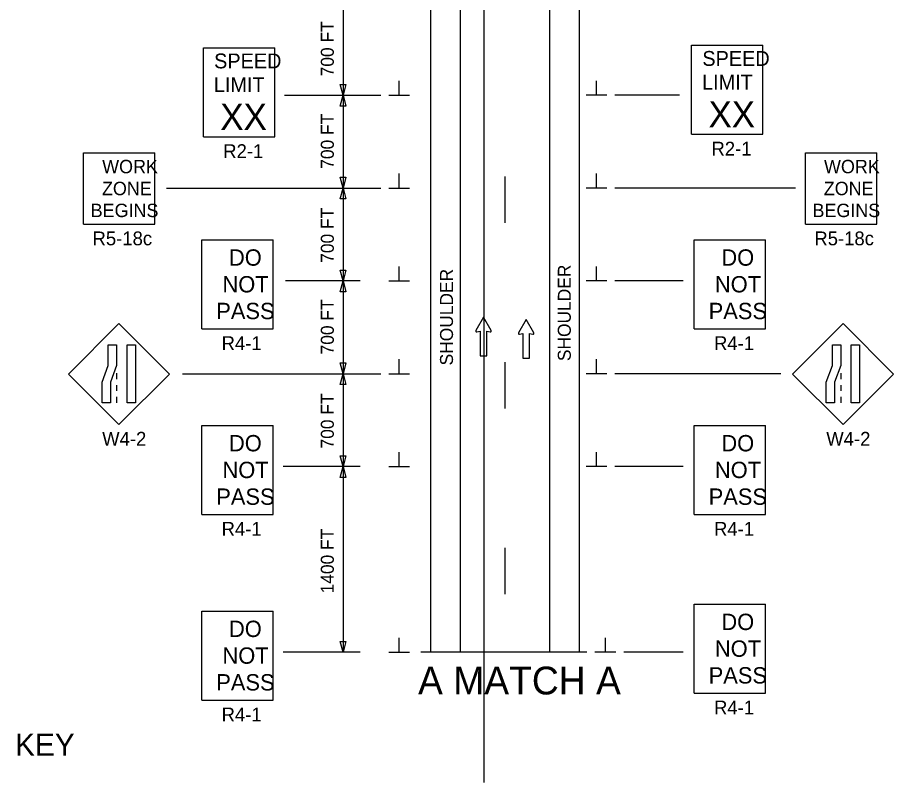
# Model space of a CAD drawing. Extents: x 15273 to 18137, y 1908 to 6555.
# Drawn here: x 15330.6 to 15802.3, y 2408.6 to 2820.6 of the extents above; entities that cross this region are included whole.
import ezdxf

# ---------------------------------------------------------------- set-up
doc = ezdxf.new("R2010")
doc.units = 0
for name, color, linetype in [('ALI_LEGAL_EX', 7, 'Continuous'), ('MT_SCRATCH_LEVEL_E', 7, 'Continuous'), ('PAVT_EDGE_EX', 7, 'Continuous'), ('TRAFFIC_SIGNS_PR', 7, 'Continuous'), ('TYPICAL_TEXT_DIMEN_EX', 7, 'Continuous'), ('TYPICAL_TEXT_DIMEN_PR', 7, 'Continuous')]:
    doc.layers.add(name, color=color, linetype=linetype)

msp = doc.modelspace()

# ---------------------------------------------------------------- linework, layer by layer
at = {"layer": 'ALI_LEGAL_EX'}
msp.add_line((15581.68, 3237.79), (15581.68, 2408.6), dxfattribs=at)
for points in [[(15593, 2735), (15593, 2710)], [(15593, 2635), (15593, 2610)], [(15593, 2535), (15593, 2510)]]:
    msp.add_lwpolyline(points, dxfattribs=at)
at = {"layer": 'MT_SCRATCH_LEVEL_E'}
for p, q in [((15581.51, 2659.29), (15577.39, 2652.05)), ((15585.65, 2652.05), (15581.51, 2659.29)), ((15604.48, 2658.02), (15600.37, 2650.78)), ((15608.63, 2650.78), (15604.48, 2658.02)), ((15577.88, 2651.37), (15579.65, 2651.68)), ((15579.65, 2651.68), (15579.65, 2638.43)), ((15583.4, 2638.43), (15583.4, 2651.68)), ((15583.4, 2651.68), (15585.17, 2651.37)), ((15600.85, 2650.1), (15602.63, 2650.41)), ((15602.63, 2650.41), (15602.63, 2637.16)), ((15606.37, 2637.16), (15606.37, 2650.41)), ((15606.37, 2650.41), (15608.15, 2650.1)), ((15579.65, 2638.43), (15583.4, 2638.43)), ((15602.63, 2637.16), (15606.37, 2637.16))]:
    msp.add_line(p, q, dxfattribs=at)
for centre, start, end in [((15577.8, 2651.83), 150.4248, 279.9638), ((15585.24, 2651.83), 260.0362, 29.7731), ((15600.78, 2650.56), 150.4248, 279.9638), ((15608.22, 2650.56), 260.0362, 29.7731)]:
    msp.add_arc(centre, 0.463, start, end, dxfattribs=at)
at = {"layer": 'PAVT_EDGE_EX'}
for p, q in [((15553, 3162.29), (15553, 2478.74)), ((15569, 3162.29), (15569, 2478.74)), ((15617, 3162.29), (15617, 2478.74)), ((15633, 3163.21), (15633, 2478.74))]:
    msp.add_line(p, q, dxfattribs=at)
at = {"layer": 'TRAFFIC_SIGNS_PR'}
for p, q in [((15430.69, 2804.37), (15469.09, 2804.37)), ((15430.69, 2756.37), (15430.69, 2804.37)), ((15469.09, 2756.37), (15469.09, 2804.37)), ((15693.59, 2805.71), (15731.99, 2805.71)), ((15693.59, 2757.71), (15693.59, 2805.71)), ((15731.99, 2757.71), (15731.99, 2805.71)), ((15430.69, 2756.37), (15469.09, 2756.37)), ((15693.59, 2757.71), (15731.99, 2757.71)), ((15366.19, 2709.37), (15366.19, 2747.77)), ((15366.19, 2747.77), (15404.59, 2747.77)), ((15404.59, 2709.37), (15404.59, 2747.77)), ((15754.87, 2709.37), (15754.87, 2747.77)), ((15754.87, 2747.77), (15793.27, 2747.77)), ((15793.27, 2709.37), (15793.27, 2747.77)), ((15366.19, 2709.37), (15404.59, 2709.37)), ((15754.87, 2709.37), (15793.27, 2709.37)), ((15429.84, 2652.95), (15429.84, 2700.95)), ((15429.84, 2700.95), (15468.24, 2700.95)), ((15468.24, 2652.95), (15468.24, 2700.95)), ((15694.98, 2652.95), (15694.98, 2700.95)), ((15694.98, 2700.95), (15733.38, 2700.95)), ((15733.38, 2652.95), (15733.38, 2700.95)), ((15385.23, 2655.75), (15358.07, 2628.6)), ((15412.38, 2628.6), (15385.23, 2655.75)), ((15775.13, 2655.75), (15747.98, 2628.6)), ((15802.28, 2628.6), (15775.13, 2655.75)), ((15429.84, 2652.95), (15468.24, 2652.95)), ((15694.98, 2652.95), (15733.38, 2652.95)), ((15358.07, 2628.6), (15385.23, 2601.45)), ((15383.98, 2629.09), (15383.98, 2625.89)), ((15385.23, 2601.45), (15412.38, 2628.6)), ((15747.98, 2628.6), (15775.13, 2601.45)), ((15773.88, 2629.09), (15773.88, 2625.89)), ((15775.13, 2601.45), (15802.28, 2628.6)), ((15383.98, 2622.69), (15383.98, 2619.49)), ((15773.88, 2622.69), (15773.88, 2619.49)), ((15383.98, 2616.29), (15383.98, 2613.09)), ((15773.88, 2616.29), (15773.88, 2613.09)), ((15429.84, 2552.95), (15429.84, 2600.95)), ((15429.84, 2600.95), (15468.24, 2600.95)), ((15468.24, 2552.95), (15468.24, 2600.95)), ((15694.98, 2552.95), (15694.98, 2600.95)), ((15694.98, 2600.95), (15733.38, 2600.95)), ((15733.38, 2552.95), (15733.38, 2600.95)), ((15429.84, 2552.95), (15468.24, 2552.95)), ((15694.98, 2552.95), (15733.38, 2552.95)), ((15694.98, 2456.71), (15694.98, 2504.71)), ((15694.98, 2504.71), (15733.38, 2504.71)), ((15733.38, 2456.71), (15733.38, 2504.71)), ((15429.84, 2452.95), (15429.84, 2500.95)), ((15429.84, 2500.95), (15468.24, 2500.95)), ((15468.24, 2452.95), (15468.24, 2500.95)), ((15429.84, 2452.95), (15468.24, 2452.95)), ((15694.98, 2456.71), (15733.38, 2456.71))]:
    msp.add_line(p, q, dxfattribs=at)
for points in [[(15383.98, 2644.34), (15383.98, 2633.15), (15380.63, 2624.27), (15380.63, 2613.09), (15376.14, 2613.09), (15376.14, 2624.27), (15379.49, 2633.15), (15379.49, 2644.34)], [(15394.11, 2644.34), (15394.11, 2613.09), (15389.62, 2613.09), (15389.62, 2644.34)], [(15773.88, 2644.34), (15773.88, 2633.15), (15770.54, 2624.27), (15770.54, 2613.09), (15766.04, 2613.09), (15766.04, 2624.27), (15769.39, 2633.15), (15769.39, 2644.34)], [(15784.02, 2644.34), (15784.02, 2613.09), (15779.52, 2613.09), (15779.52, 2644.34)]]:
    msp.add_lwpolyline(points, close=True, dxfattribs=at)
at = {"layer": 'TYPICAL_TEXT_DIMEN_PR'}
for p, q in [((15505.88, 2828.74), (15505.88, 2778.74)), ((15505.88, 2778.74), (15504.31, 2784.61)), ((15504.31, 2784.61), (15505.88, 2784.61)), ((15505.88, 2784.61), (15507.45, 2784.61)), ((15507.45, 2784.61), (15505.88, 2778.74)), ((15536.12, 2778.74), (15536.12, 2786.53)), ((15642.37, 2778.74), (15642.37, 2786.53)), ((15474.36, 2778.74), (15526.25, 2778.74)), ((15504.31, 2772.88), (15505.88, 2778.74)), ((15504.31, 2772.88), (15505.88, 2778.74)), ((15505.88, 2778.74), (15505.88, 2728.74)), ((15505.88, 2778.74), (15507.45, 2772.88)), ((15505.88, 2778.74), (15507.45, 2772.88)), ((15530.5, 2778.74), (15541.75, 2778.74)), ((15648, 2778.74), (15636.75, 2778.74)), ((15687.08, 2778.74), (15652.25, 2778.74)), ((15505.88, 2772.88), (15504.31, 2772.88)), ((15505.88, 2772.88), (15504.31, 2772.88)), ((15507.45, 2772.88), (15505.88, 2772.88)), ((15507.45, 2772.88), (15505.88, 2772.88)), ((15536.12, 2728.74), (15536.12, 2736.53)), ((15642.37, 2728.74), (15642.37, 2736.53)), ((15505.88, 2728.74), (15504.31, 2734.61)), ((15504.31, 2734.61), (15505.88, 2734.61)), ((15505.88, 2728.74), (15504.31, 2734.61)), ((15504.31, 2734.61), (15505.88, 2734.61)), ((15505.88, 2734.61), (15507.45, 2734.61)), ((15507.45, 2734.61), (15505.88, 2728.74)), ((15505.88, 2734.61), (15507.45, 2734.61)), ((15507.45, 2734.61), (15505.88, 2728.74)), ((15410.88, 2728.74), (15526.25, 2728.74)), ((15504.31, 2722.88), (15505.88, 2728.74)), ((15505.88, 2728.74), (15505.88, 2678.74)), ((15505.88, 2728.74), (15507.45, 2722.88)), ((15530.5, 2728.74), (15541.75, 2728.74)), ((15648, 2728.74), (15636.75, 2728.74)), ((15749.59, 2728.74), (15652.25, 2728.74)), ((15505.88, 2722.88), (15504.31, 2722.88)), ((15507.45, 2722.88), (15505.88, 2722.88)), ((15505.88, 2678.74), (15504.31, 2684.61)), ((15504.31, 2684.61), (15505.88, 2684.61)), ((15505.88, 2684.61), (15507.45, 2684.61)), ((15507.45, 2684.61), (15505.88, 2678.74)), ((15536.12, 2678.74), (15536.12, 2686.53)), ((15642.37, 2678.74), (15642.37, 2686.53)), ((15515.11, 2678.74), (15474.99, 2678.74)), ((15504.31, 2672.88), (15505.88, 2678.74)), ((15505.88, 2678.74), (15505.88, 2628.74)), ((15505.88, 2678.74), (15507.45, 2672.88)), ((15530.5, 2678.74), (15541.75, 2678.74)), ((15648, 2678.74), (15636.75, 2678.74)), ((15688.96, 2678.74), (15652.25, 2678.74)), ((15505.88, 2672.88), (15504.31, 2672.88)), ((15507.45, 2672.88), (15505.88, 2672.88)), ((15505.88, 2628.74), (15504.31, 2634.61)), ((15504.31, 2634.61), (15505.88, 2634.61)), ((15505.88, 2628.74), (15504.31, 2634.61)), ((15504.31, 2634.61), (15505.88, 2634.61)), ((15505.88, 2634.61), (15507.45, 2634.61)), ((15507.45, 2634.61), (15505.88, 2628.74)), ((15505.88, 2634.61), (15507.45, 2634.61)), ((15507.45, 2634.61), (15505.88, 2628.74)), ((15536.12, 2628.74), (15536.12, 2636.53)), ((15642.37, 2628.74), (15642.37, 2636.53)), ((15419.37, 2628.74), (15526.25, 2628.74)), ((15504.31, 2622.88), (15505.88, 2628.74)), ((15505.88, 2628.74), (15505.88, 2578.74)), ((15505.88, 2628.74), (15507.45, 2622.88)), ((15530.5, 2628.74), (15541.75, 2628.74)), ((15648, 2628.74), (15636.75, 2628.74)), ((15741.65, 2628.74), (15652.25, 2628.74)), ((15505.88, 2622.88), (15504.31, 2622.88)), ((15507.45, 2622.88), (15505.88, 2622.88)), ((15536.12, 2578.74), (15536.12, 2586.53)), ((15642.37, 2578.74), (15642.37, 2586.53)), ((15505.88, 2578.74), (15504.31, 2584.61)), ((15504.31, 2584.61), (15505.88, 2584.61)), ((15505.88, 2584.61), (15507.45, 2584.61)), ((15507.45, 2584.61), (15505.88, 2578.74)), ((15515.11, 2578.74), (15473.68, 2578.74)), ((15504.31, 2572.88), (15505.88, 2578.74)), ((15505.88, 2578.74), (15505.88, 2478.74)), ((15505.88, 2578.74), (15507.45, 2572.88)), ((15530.5, 2578.74), (15541.75, 2578.74)), ((15648, 2578.74), (15636.75, 2578.74)), ((15688.96, 2578.74), (15652.25, 2578.74)), ((15505.88, 2572.88), (15504.31, 2572.88)), ((15507.45, 2572.88), (15505.88, 2572.88)), ((15536.12, 2478.74), (15536.12, 2486.53)), ((15647.13, 2478.74), (15647.13, 2486.53)), ((15505.88, 2478.74), (15504.31, 2484.61)), ((15504.31, 2484.61), (15505.88, 2484.61)), ((15505.88, 2484.61), (15507.45, 2484.61)), ((15507.45, 2484.61), (15505.88, 2478.74)), ((15515.11, 2478.74), (15473.68, 2478.74)), ((15530.5, 2478.74), (15541.75, 2478.74)), ((15637.19, 2478.74), (15547.76, 2478.74)), ((15652.75, 2478.74), (15641.5, 2478.74)), ((15688.96, 2478.74), (15657.07, 2478.74))]:
    msp.add_line(p, q, dxfattribs=at)

# ---------------------------------------------------------------- texts
at = {"layer": 'TRAFFIC_SIGNS_PR'}
for s, height, p in [('SPEED', 8, (15699.36, 2794.58)), ('SPEED', 8, (15436.46, 2793.23)), ('LIMIT', 8, (15436.3, 2780.43)), ('LIMIT', 8, (15699.2, 2781.78)), ('XX', 14.031, (15439.8, 2760.12)), ('XX', 14.031, (15702.7, 2761.47)), ('R2-1', 7.44, (15441.37, 2744.93)), ('R2-1', 7.44, (15704.27, 2746.27)), ('WORK', 7.217, (15376.19, 2736.74)), ('WORK', 7.217, (15764.87, 2736.74)), ('ZONE', 7.217, (15376.07, 2724.93)), ('ZONE', 7.217, (15764.75, 2724.93)), ('BEGINS', 7.217, (15370, 2713.12)), ('BEGINS', 7.217, (15758.68, 2713.12)), ('R5-18c', 7.44, (15371, 2697.93)), ('R5-18c', 7.44, (15759.68, 2697.93)), ('DO', 8.8, (15444.47, 2686.95)), ('DO', 8.8, (15709.61, 2686.95)), ('NOT', 8.8, (15440.98, 2672.55)), ('NOT', 8.8, (15706.12, 2672.55)), ('PASS', 8.8, (15437.63, 2658.15)), ('PASS', 8.8, (15702.77, 2658.15)), ('R4-1', 7.44, (15440.51, 2641.51)), ('R4-1', 7.44, (15705.65, 2641.51)), ('W4-2', 7.44, (15376.18, 2590.01)), ('DO', 8.8, (15444.47, 2586.95)), ('DO', 8.8, (15709.61, 2586.95)), ('W4-2', 7.44, (15766.09, 2590.01)), ('NOT', 8.8, (15440.98, 2572.55)), ('NOT', 8.8, (15706.12, 2572.55)), ('PASS', 8.8, (15437.63, 2558.15)), ('PASS', 8.8, (15702.77, 2558.15)), ('R4-1', 7.44, (15440.51, 2541.51)), ('R4-1', 7.44, (15705.65, 2541.51)), ('DO', 8.8, (15444.47, 2486.95)), ('DO', 8.8, (15709.61, 2490.71)), ('NOT', 8.8, (15440.98, 2472.55)), ('NOT', 8.8, (15706.12, 2476.31)), ('PASS', 8.8, (15437.63, 2458.15)), ('PASS', 8.8, (15702.77, 2461.91)), ('R4-1', 7.44, (15440.51, 2441.51)), ('R4-1', 7.44, (15705.65, 2445.27))]:
    msp.add_text(s, height=height, dxfattribs=at).set_placement(p)
at = {"layer": 'TYPICAL_TEXT_DIMEN_EX'}
msp.add_text('KEY', height=12, dxfattribs=at).set_placement((15329.28, 2422.97))
at = {"layer": 'TYPICAL_TEXT_DIMEN_PR'}
for s, p in [('700 FT', (15500.92, 2788.92)), ('700 FT', (15500.92, 2739.16)), ('700 FT', (15500.92, 2688.5)), ('SHOULDER', (15565.1, 2633.23)), ('SHOULDER', (15628.53, 2635.54)), ('700 FT', (15500.92, 2639.16)), ('700 FT', (15500.92, 2588.5)), ('1400 FT', (15500.92, 2510.43))]:
    msp.add_text(s, height=7, rotation=90, dxfattribs=at).set_placement(p)
msp.add_text('A MATCH A', height=15, dxfattribs=at).set_placement((15546.27, 2456.02))

doc.saveas('drawing.dxf')
